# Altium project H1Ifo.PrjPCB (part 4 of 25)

## Sheet IfoTcs1.SchDoc: D1800185
size C; Engineer: Daniel Sigg; DocumentNumber: 7; Revision: 4; SheetNumber: 7; SheetTotal: 8
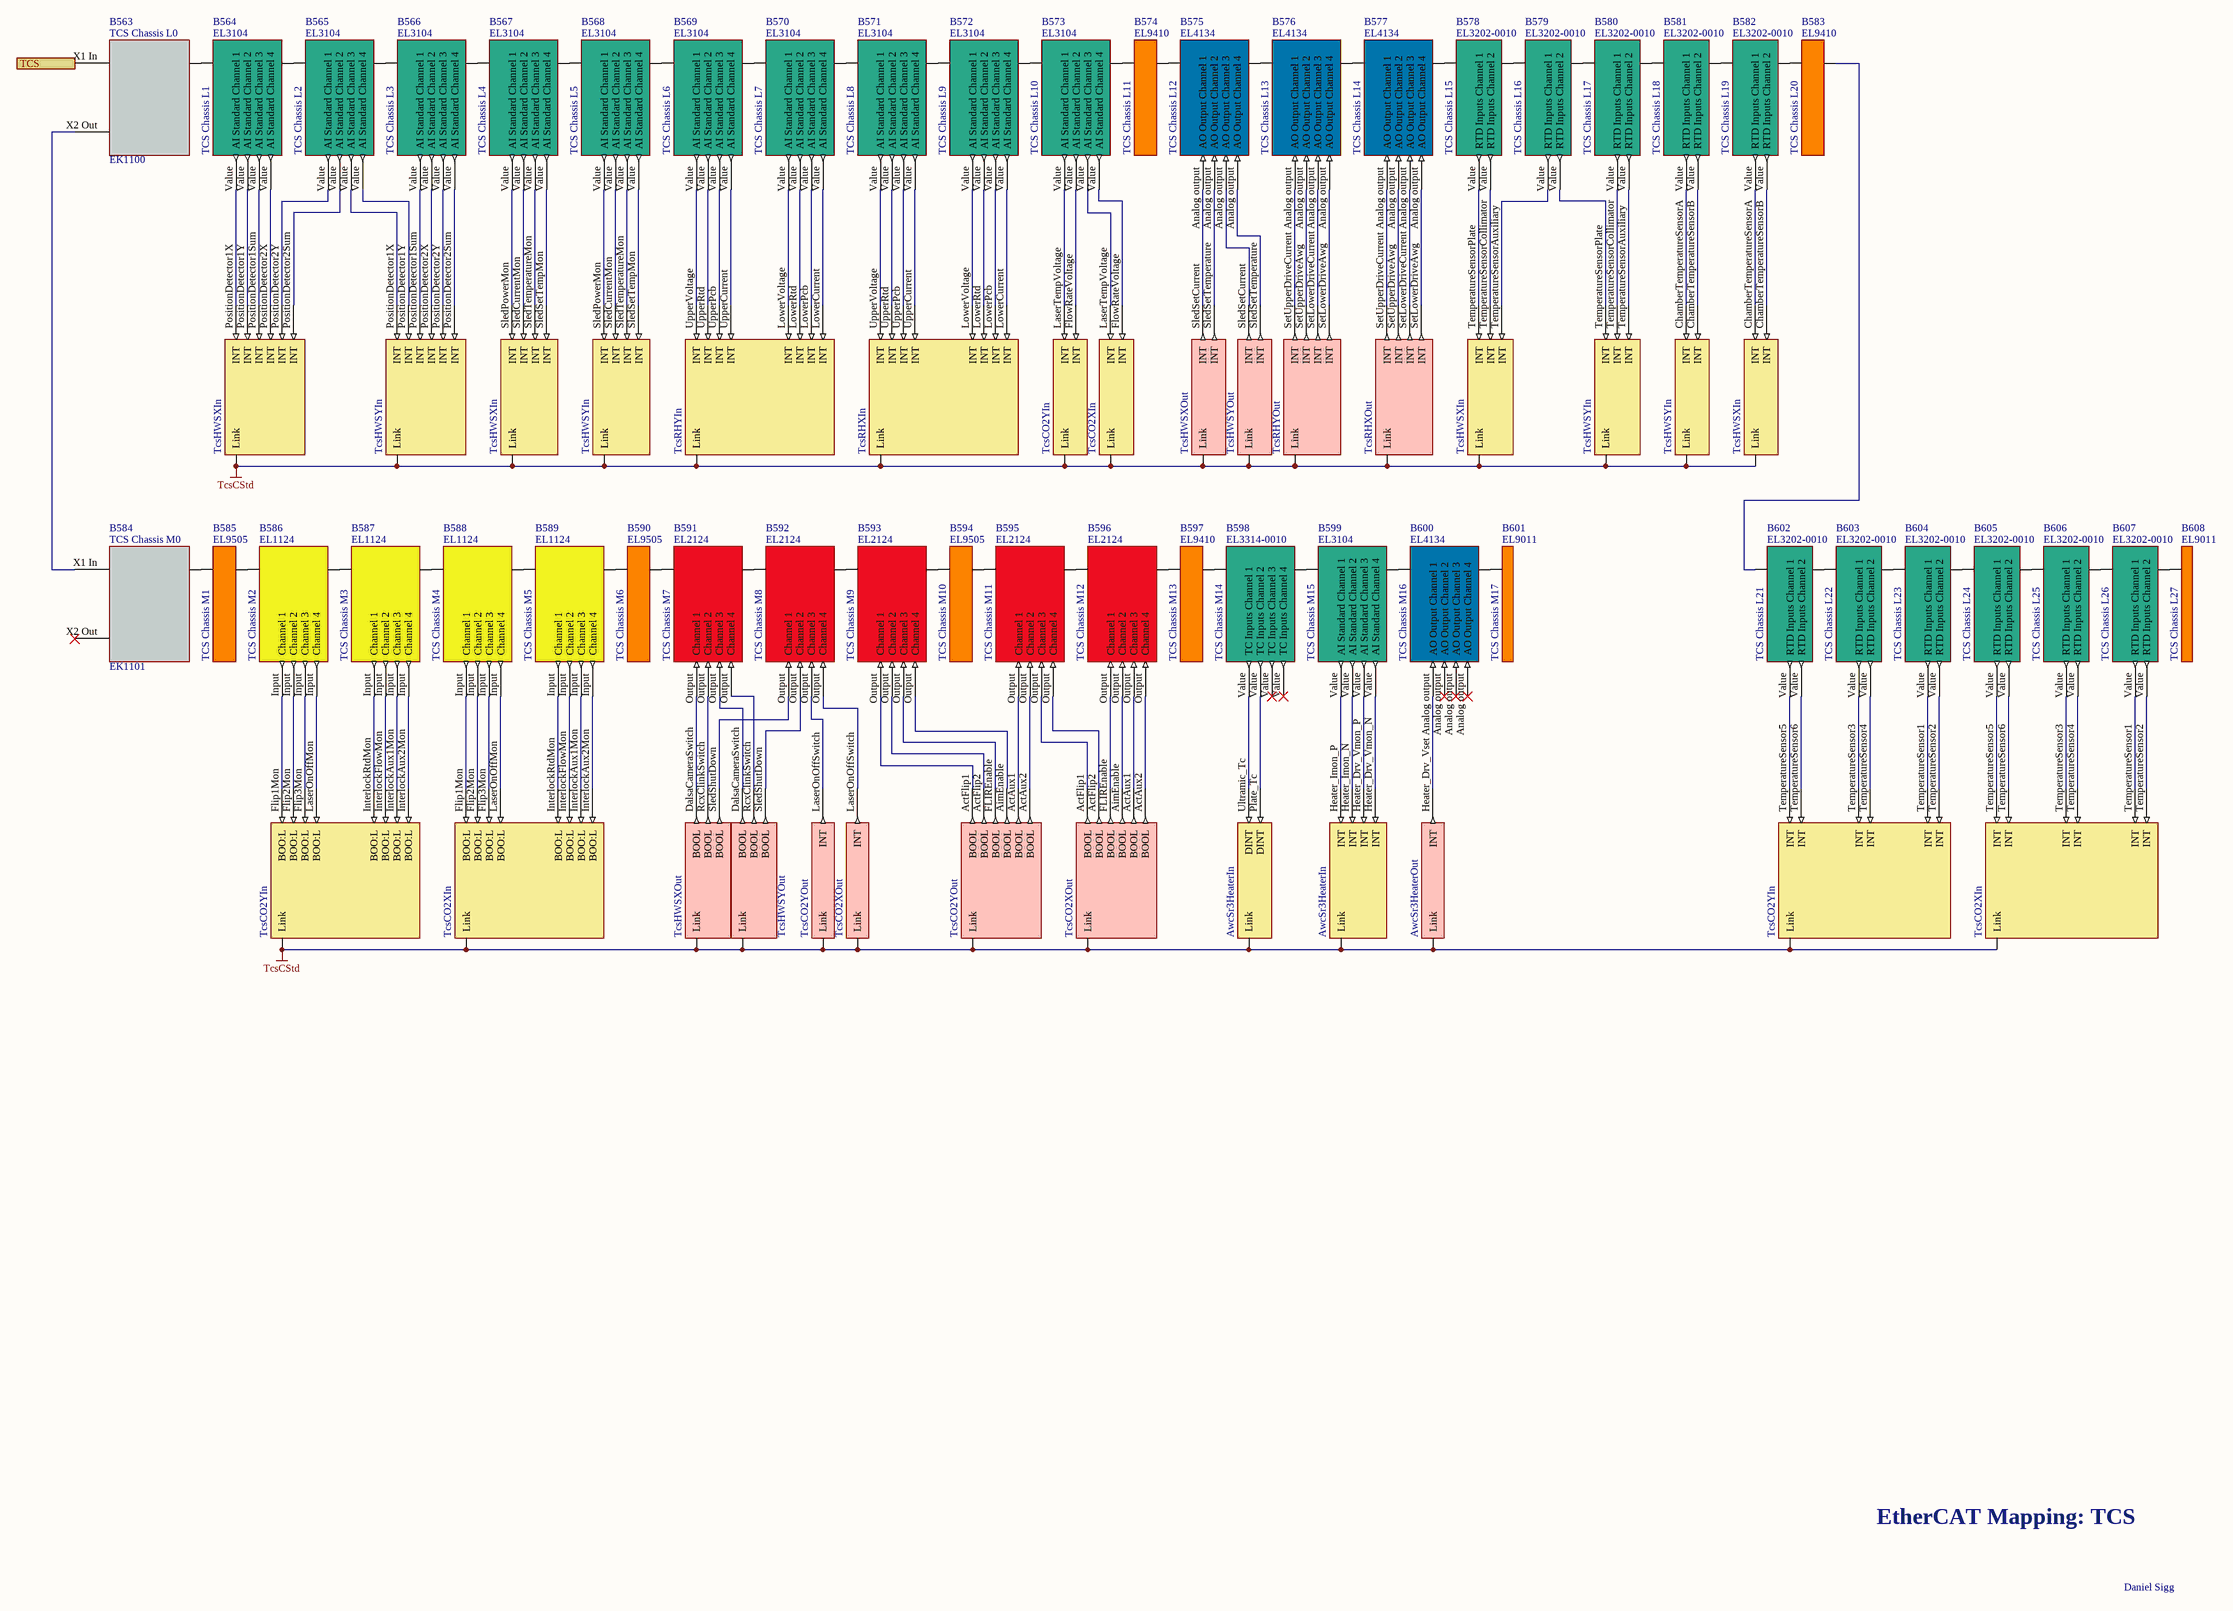
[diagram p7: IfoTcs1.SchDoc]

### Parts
B563  TCS Chassis L0  Part Number: EK1100
B564  TCS Chassis L1  Part Number: EL3104  (mechanical)
B565  TCS Chassis L2  Part Number: EL3104  (mechanical)
B566  TCS Chassis L3  Part Number: EL3104  (mechanical)
B567  TCS Chassis L4  Part Number: EL3104  (mechanical)
B568  TCS Chassis L5  Part Number: EL3104  (mechanical)
B569  TCS Chassis L6  Part Number: EL3104  (mechanical)
B570  TCS Chassis L7  Part Number: EL3104  (mechanical)
B571  TCS Chassis L8  Part Number: EL3104  (mechanical)
B572  TCS Chassis L9  Part Number: EL3104  (mechanical)
B573  TCS Chassis L10  Part Number: EL3104  (mechanical)
B574  TCS Chassis L11  Part Number: EL9410  (mechanical)
B575  TCS Chassis L12  Part Number: EL4134  (mechanical)
B576  TCS Chassis L13  Part Number: EL4134  (mechanical)
B577  TCS Chassis L14  Part Number: EL4134  (mechanical)
B578  TCS Chassis L15  Part Number: EL3202-0010  (mechanical)
B579  TCS Chassis L16  Part Number: EL3202-0010  (mechanical)
B580  TCS Chassis L17  Part Number: EL3202-0010  (mechanical)
B581  TCS Chassis L18  Part Number: EL3202-0010  (mechanical)
B582  TCS Chassis L19  Part Number: EL3202-0010  (mechanical)
B583  TCS Chassis L20  Part Number: EL9410  (mechanical)
B584  TCS Chassis M0  Part Number: EK1101
B585  TCS Chassis M1  Part Number: EL9505  (mechanical)
B586  TCS Chassis M2  Part Number: EL1124  (mechanical)
B587  TCS Chassis M3  Part Number: EL1124  (mechanical)
B588  TCS Chassis M4  Part Number: EL1124  (mechanical)
B589  TCS Chassis M5  Part Number: EL1124  (mechanical)
B590  TCS Chassis M6  Part Number: EL9505  (mechanical)
B591  TCS Chassis M7  Part Number: EL2124  (mechanical)
B592  TCS Chassis M8  Part Number: EL2124  (mechanical)
B593  TCS Chassis M9  Part Number: EL2124  (mechanical)
B594  TCS Chassis M10  Part Number: EL9505  (mechanical)
B595  TCS Chassis M11  Part Number: EL2124  (mechanical)
B596  TCS Chassis M12  Part Number: EL2124  (mechanical)
B597  TCS Chassis M13  Part Number: EL9410  (mechanical)
B598  TCS Chassis M14  Part Number: EL3314-0010  (mechanical)
B599  TCS Chassis M15  Part Number: EL3104  (mechanical)
B600  TCS Chassis M16  Part Number: EL4134  (mechanical)
B601  TCS Chassis M17  Part Number: EL9011  (mechanical)
B602  TCS Chassis L21  Part Number: EL3202-0010  (mechanical)
B603  TCS Chassis L22  Part Number: EL3202-0010  (mechanical)
B604  TCS Chassis L23  Part Number: EL3202-0010  (mechanical)
B605  TCS Chassis L24  Part Number: EL3202-0010  (mechanical)
B606  TCS Chassis L25  Part Number: EL3202-0010  (mechanical)
B607  TCS Chassis L26  Part Number: EL3202-0010  (mechanical)
B608  TCS Chassis L27  Part Number: EL9011  (mechanical)
V519  TcsHWSXIn  (parts A,B,C,D of 4)  (no BOM)
V520  TcsHWSYIn  (parts A,B,C,D of 4)  (no BOM)
V521  TcsRHYIn  (no BOM)
V522  TcsRHXIn  (no BOM)
V523  TcsRHYOut  (no BOM)
V524  TcsRHXOut  (no BOM)
V525  AwcSr3HeaterOut  (no BOM)
V587  TcsHWSXOut  (parts A,B of 2)  (no BOM)
V588  TcsHWSYOut  (parts A,B of 2)  (no BOM)
V589  TcsCO2YIn  (parts A,B,C of 3)  (no BOM)
V590  TcsCO2XIn  (parts A,B,C of 3)  (no BOM)
V591  TcsCO2YOut  (parts A,B of 2)  (no BOM)
V592  TcsCO2XOut  (parts A,B of 2)  (no BOM)
V593  AwcSr3HeaterIn  (parts A,B of 2)  (no BOM)

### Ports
TCS

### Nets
TcsCStd: V519.0(Link) V519.1(Link) V519.2(Link) V519.4(Link) V520.0(Link) V520.1(Link) V520.2(Link) V520.4(Link) V521.0(Link) V522.0(Link) V523.0(Link) V524.0(Link) V525.0(Link) V587.0(Link) V587.1(Link) V588.0(Link) V588.1(Link) V589.0(Link) V589.1(Link) V589.2(Link) V590.0(Link) V590.1(Link) V590.2(Link) V591.0(Link) V591.1(Link) V592.0(Link) V592.1(Link) V593.0(Link) V593.1(Link)
NetB554_X2 Out: B563.X1_In(A) ; port TCS
NetB563_Ebus: B563.Ebus(B) B564.Ebus(A)
NetB563_X2 Out: B563.X2_Out(C) B584.X1_In(A)
NetB564_Ebus: B564.Ebus(B) B565.Ebus(A)
NetB564_Value: B564.Value(AI_Standard_Channel_1) V519.PositionDetector1X(INT)
NetB564_Value: B564.Value(AI_Standard_Channel_2) V519.PositionDetector1Y(INT)  [a separate net that carries the same name]
NetB564_Value: B564.Value(AI_Standard_Channel_3) V519.PositionDetector1Sum(INT)  [a separate net that carries the same name]
NetB564_Value: B564.Value(AI_Standard_Channel_4) V519.PositionDetector2X(INT)  [a separate net that carries the same name]
NetB565_Ebus: B565.Ebus(B) B566.Ebus(A)
NetB565_Value: B565.Value(AI_Standard_Channel_1) V519.PositionDetector2Y(INT)
NetB565_Value: B565.Value(AI_Standard_Channel_2) V519.PositionDetector2Sum(INT)  [a separate net that carries the same name]
NetB565_Value: B565.Value(AI_Standard_Channel_3) V520.PositionDetector1X(INT)  [a separate net that carries the same name]
NetB565_Value: B565.Value(AI_Standard_Channel_4) V520.PositionDetector1Y(INT)  [a separate net that carries the same name]
NetB566_Ebus: B566.Ebus(B) B567.Ebus(A)
NetB566_Value: B566.Value(AI_Standard_Channel_1) V520.PositionDetector1Sum(INT)
NetB566_Value: B566.Value(AI_Standard_Channel_2) V520.PositionDetector2X(INT)  [a separate net that carries the same name]
NetB566_Value: B566.Value(AI_Standard_Channel_3) V520.PositionDetector2Y(INT)  [a separate net that carries the same name]
NetB566_Value: B566.Value(AI_Standard_Channel_4) V520.PositionDetector2Sum(INT)  [a separate net that carries the same name]
NetB567_Ebus: B567.Ebus(B) B568.Ebus(A)
NetB567_Value: B567.Value(AI_Standard_Channel_1) V519.SledPowerMon(INT)
NetB567_Value: B567.Value(AI_Standard_Channel_2) V519.SledCurrentMon(INT)  [a separate net that carries the same name]
NetB567_Value: B567.Value(AI_Standard_Channel_3) V519.SledTemperatureMon(INT)  [a separate net that carries the same name]
NetB567_Value: B567.Value(AI_Standard_Channel_4) V519.SledSetTempMon(INT)  [a separate net that carries the same name]
NetB568_Ebus: B568.Ebus(B) B569.Ebus(A)
NetB568_Value: B568.Value(AI_Standard_Channel_1) V520.SledPowerMon(INT)
NetB568_Value: B568.Value(AI_Standard_Channel_2) V520.SledCurrentMon(INT)  [a separate net that carries the same name]
NetB568_Value: B568.Value(AI_Standard_Channel_3) V520.SledTemperatureMon(INT)  [a separate net that carries the same name]
NetB568_Value: B568.Value(AI_Standard_Channel_4) V520.SledSetTempMon(INT)  [a separate net that carries the same name]
NetB569_Ebus: B569.Ebus(B) B570.Ebus(A)
NetB569_Value: B569.Value(AI_Standard_Channel_1) V521.UpperVoltage(INT)
NetB569_Value: B569.Value(AI_Standard_Channel_2) V521.UpperRtd(INT)  [a separate net that carries the same name]
NetB569_Value: B569.Value(AI_Standard_Channel_3) V521.UpperPcb(INT)  [a separate net that carries the same name]
NetB569_Value: B569.Value(AI_Standard_Channel_4) V521.UpperCurrent(INT)  [a separate net that carries the same name]
NetB570_Ebus: B570.Ebus(B) B571.Ebus(A)
NetB570_Value: B570.Value(AI_Standard_Channel_1) V521.LowerVoltage(INT)
NetB570_Value: B570.Value(AI_Standard_Channel_2) V521.LowerRtd(INT)  [a separate net that carries the same name]
NetB570_Value: B570.Value(AI_Standard_Channel_3) V521.LowerPcb(INT)  [a separate net that carries the same name]
NetB570_Value: B570.Value(AI_Standard_Channel_4) V521.LowerCurrent(INT)  [a separate net that carries the same name]
NetB571_Ebus: B571.Ebus(B) B572.Ebus(A)
NetB571_Value: B571.Value(AI_Standard_Channel_1) V522.UpperVoltage(INT)
NetB571_Value: B571.Value(AI_Standard_Channel_2) V522.UpperRtd(INT)  [a separate net that carries the same name]
NetB571_Value: B571.Value(AI_Standard_Channel_3) V522.UpperPcb(INT)  [a separate net that carries the same name]
NetB571_Value: B571.Value(AI_Standard_Channel_4) V522.UpperCurrent(INT)  [a separate net that carries the same name]
NetB572_Ebus: B572.Ebus(B) B573.Ebus(A)
NetB572_Value: B572.Value(AI_Standard_Channel_1) V522.LowerVoltage(INT)
NetB572_Value: B572.Value(AI_Standard_Channel_2) V522.LowerRtd(INT)  [a separate net that carries the same name]
NetB572_Value: B572.Value(AI_Standard_Channel_3) V522.LowerPcb(INT)  [a separate net that carries the same name]
NetB572_Value: B572.Value(AI_Standard_Channel_4) V522.LowerCurrent(INT)  [a separate net that carries the same name]
NetB573_Ebus: B573.Ebus(B) B574.Ebus(A)
NetB573_Value: B573.Value(AI_Standard_Channel_1) V589.LaserTempVoltage(INT)
NetB573_Value: B573.Value(AI_Standard_Channel_2) V589.FlowRateVoltage(INT)  [a separate net that carries the same name]
NetB573_Value: B573.Value(AI_Standard_Channel_3) V590.LaserTempVoltage(INT)  [a separate net that carries the same name]
NetB573_Value: B573.Value(AI_Standard_Channel_4) V590.FlowRateVoltage(INT)  [a separate net that carries the same name]
NetB574_Ebus: B574.Ebus(B) B575.Ebus(A)
NetB575_Analog output: B575.Analog_output(AO_Output_Channel_1) V587.SledSetCurrent(INT)
NetB575_Analog output: B575.Analog_output(AO_Output_Channel_2) V587.SledSetTemperature(INT)  [a separate net that carries the same name]
NetB575_Analog output: B575.Analog_output(AO_Output_Channel_3) V588.SledSetCurrent(INT)  [a separate net that carries the same name]
NetB575_Analog output: B575.Analog_output(AO_Output_Channel_4) V588.SledSetTemperature(INT)  [a separate net that carries the same name]
NetB575_Ebus: B575.Ebus(B) B576.Ebus(A)
NetB576_Analog output: B576.Analog_output(AO_Output_Channel_1) V523.SetUpperDriveCurrent(INT)
NetB576_Analog output: B576.Analog_output(AO_Output_Channel_2) V523.SetUpperDriveAwg(INT)  [a separate net that carries the same name]
NetB576_Analog output: B576.Analog_output(AO_Output_Channel_3) V523.SetLowerDriveCurrent(INT)  [a separate net that carries the same name]
NetB576_Analog output: B576.Analog_output(AO_Output_Channel_4) V523.SetLowerDriveAwg(INT)  [a separate net that carries the same name]
NetB576_Ebus: B576.Ebus(B) B577.Ebus(A)
NetB577_Analog output: B577.Analog_output(AO_Output_Channel_1) V524.SetUpperDriveCurrent(INT)
NetB577_Analog output: B577.Analog_output(AO_Output_Channel_2) V524.SetUpperDriveAwg(INT)  [a separate net that carries the same name]
NetB577_Analog output: B577.Analog_output(AO_Output_Channel_3) V524.SetLowerDriveCurrent(INT)  [a separate net that carries the same name]
NetB577_Analog output: B577.Analog_output(AO_Output_Channel_4) V524.SetLowerDriveAwg(INT)  [a separate net that carries the same name]
NetB577_Ebus: B577.Ebus(B) B578.Ebus(A)
NetB578_Ebus: B578.Ebus(B) B579.Ebus(A)
NetB578_Value: B578.Value(RTD_Inputs_Channel_1) V519.TemperatureSensorPlate(INT)
NetB578_Value: B578.Value(RTD_Inputs_Channel_2) V519.TemperatureSensorCollimator(INT)  [a separate net that carries the same name]
NetB579_Ebus: B579.Ebus(B) B580.Ebus(A)
NetB579_Value: B579.Value(RTD_Inputs_Channel_1) V519.TemperatureSensorAuxiliary(INT)
NetB579_Value: B579.Value(RTD_Inputs_Channel_2) V520.TemperatureSensorPlate(INT)  [a separate net that carries the same name]
NetB580_Ebus: B580.Ebus(B) B581.Ebus(A)
NetB580_Value: B580.Value(RTD_Inputs_Channel_1) V520.TemperatureSensorCollimator(INT)
NetB580_Value: B580.Value(RTD_Inputs_Channel_2) V520.TemperatureSensorAuxiliary(INT)  [a separate net that carries the same name]
NetB581_Ebus: B581.Ebus(B) B582.Ebus(A)
NetB581_Value: B581.Value(RTD_Inputs_Channel_1) V520.ChamberTemperatureSensorA(INT)
NetB581_Value: B581.Value(RTD_Inputs_Channel_2) V520.ChamberTemperatureSensorB(INT)  [a separate net that carries the same name]
NetB582_Ebus: B582.Ebus(B) B583.Ebus(A)
NetB582_Value: B582.Value(RTD_Inputs_Channel_1) V519.ChamberTemperatureSensorA(INT)
NetB582_Value: B582.Value(RTD_Inputs_Channel_2) V519.ChamberTemperatureSensorB(INT)  [a separate net that carries the same name]
NetB583_Ebus: B583.Ebus(B) B602.Ebus(A)
NetB584_Ebus: B584.Ebus(B) B585.Ebus(A)
NetB585_Ebus: B585.Ebus(B) B586.Ebus(A)
NetB586_Ebus: B586.Ebus(B) B587.Ebus(A)
NetB586_Input: B586.Input(Channel_1) V589.Flip1Mon(BOO:L)
NetB586_Input: B586.Input(Channel_2) V589.Flip2Mon(BOO:L)  [a separate net that carries the same name]
NetB586_Input: B586.Input(Channel_3) V589.Flip3Mon(BOO:L)  [a separate net that carries the same name]
NetB586_Input: B586.Input(Channel_4) V589.LaserOnOffMon(BOO:L)  [a separate net that carries the same name]
NetB587_Ebus: B587.Ebus(B) B588.Ebus(A)
NetB587_Input: B587.Input(Channel_1) V589.InterlockRtdMon(BOO:L)
NetB587_Input: B587.Input(Channel_2) V589.InterlockFlowMon(BOO:L)  [a separate net that carries the same name]
NetB587_Input: B587.Input(Channel_3) V589.InterlockAux1Mon(BOO:L)  [a separate net that carries the same name]
NetB587_Input: B587.Input(Channel_4) V589.InterlockAux2Mon(BOO:L)  [a separate net that carries the same name]
NetB588_Ebus: B588.Ebus(B) B589.Ebus(A)
NetB588_Input: B588.Input(Channel_1) V590.Flip1Mon(BOO:L)
NetB588_Input: B588.Input(Channel_2) V590.Flip2Mon(BOO:L)  [a separate net that carries the same name]
NetB588_Input: B588.Input(Channel_3) V590.Flip3Mon(BOO:L)  [a separate net that carries the same name]
NetB588_Input: B588.Input(Channel_4) V590.LaserOnOffMon(BOO:L)  [a separate net that carries the same name]
NetB589_Ebus: B589.Ebus(B) B590.Ebus(A)
NetB589_Input: B589.Input(Channel_1) V590.InterlockRtdMon(BOO:L)
NetB589_Input: B589.Input(Channel_2) V590.InterlockFlowMon(BOO:L)  [a separate net that carries the same name]
NetB589_Input: B589.Input(Channel_3) V590.InterlockAux1Mon(BOO:L)  [a separate net that carries the same name]
NetB589_Input: B589.Input(Channel_4) V590.InterlockAux2Mon(BOO:L)  [a separate net that carries the same name]
NetB590_Ebus: B590.Ebus(B) B591.Ebus(A)
NetB591_Ebus: B591.Ebus(B) B592.Ebus(A)
NetB591_Output: B591.Output(Channel_1) V587.DalsaCameraSwitch(BOOL)
NetB591_Output: B591.Output(Channel_2) V587.RcxClinkSwitch(BOOL)  [a separate net that carries the same name]
NetB591_Output: B591.Output(Channel_3) V588.DalsaCameraSwitch(BOOL)  [a separate net that carries the same name]
NetB591_Output: B591.Output(Channel_4) V588.RcxClinkSwitch(BOOL)  [a separate net that carries the same name]
NetB592_Ebus: B592.Ebus(B) B593.Ebus(A)
NetB592_Output: B592.Output(Channel_1) V587.SledShutDown(BOOL)
NetB592_Output: B592.Output(Channel_2) V588.SledShutDown(BOOL)  [a separate net that carries the same name]
NetB592_Output: B592.Output(Channel_3) V591.LaserOnOffSwitch(INT)  [a separate net that carries the same name]
NetB592_Output: B592.Output(Channel_4) V592.LaserOnOffSwitch(INT)  [a separate net that carries the same name]
NetB593_Ebus: B593.Ebus(B) B594.Ebus(A)
NetB593_Output: B593.Output(Channel_1) V591.ActFlip1(BOOL)
NetB593_Output: B593.Output(Channel_2) V591.ActFlip2(BOOL)  [a separate net that carries the same name]
NetB593_Output: B593.Output(Channel_3) V591.FLIREnable(BOOL)  [a separate net that carries the same name]
NetB593_Output: B593.Output(Channel_4) V591.AimEnable(BOOL)  [a separate net that carries the same name]
NetB594_Ebus: B594.Ebus(B) B595.Ebus(A)
NetB595_Ebus: B595.Ebus(B) B596.Ebus(A)
NetB595_Output: B595.Output(Channel_1) V591.ActAux1(BOOL)
NetB595_Output: B595.Output(Channel_2) V591.ActAux2(BOOL)  [a separate net that carries the same name]
NetB595_Output: B595.Output(Channel_3) V592.ActFlip1(BOOL)  [a separate net that carries the same name]
NetB595_Output: B595.Output(Channel_4) V592.ActFlip2(BOOL)  [a separate net that carries the same name]
NetB596_Ebus: B596.Ebus(B) B597.Ebus(A)
NetB596_Output: B596.Output(Channel_1) V592.FLIREnable(BOOL)
NetB596_Output: B596.Output(Channel_2) V592.AimEnable(BOOL)  [a separate net that carries the same name]
NetB596_Output: B596.Output(Channel_3) V592.ActAux1(BOOL)  [a separate net that carries the same name]
NetB596_Output: B596.Output(Channel_4) V592.ActAux2(BOOL)  [a separate net that carries the same name]
NetB597_Ebus: B597.Ebus(B) B598.Ebus(A)
NetB598_Ebus: B598.Ebus(B) B599.Ebus(A)
NetB598_Value: B598.Value(TC_Inputs_Channel_1) V593.Ultramic_Tc(DINT)
NetB598_Value: B598.Value(TC_Inputs_Channel_2) V593.Plate_Tc(DINT)  [a separate net that carries the same name]
NetB599_Ebus: B599.Ebus(B) B600.Ebus(A)
NetB599_Value: B599.Value(AI_Standard_Channel_1) V593.Heater_Imon_P(INT)
NetB599_Value: B599.Value(AI_Standard_Channel_2) V593.Heater_Imon_N(INT)  [a separate net that carries the same name]
NetB599_Value: B599.Value(AI_Standard_Channel_3) V593.Heater_Drv_Vmon_P(INT)  [a separate net that carries the same name]
NetB599_Value: B599.Value(AI_Standard_Channel_4) V593.Heater_Drv_Vmon_N(INT)  [a separate net that carries the same name]
NetB600_Analog output: B600.Analog_output(AO_Output_Channel_1) V525.Heater_Drv_Vset(INT)
NetB600_Ebus: B600.Ebus(B) B601.Ebus(A)
NetB602_Ebus: B602.Ebus(B) B603.Ebus(A)
NetB602_Value: B602.Value(RTD_Inputs_Channel_1) V589.TemperatureSensor5(INT)
NetB602_Value: B602.Value(RTD_Inputs_Channel_2) V589.TemperatureSensor6(INT)  [a separate net that carries the same name]
NetB603_Ebus: B603.Ebus(B) B604.Ebus(A)
NetB603_Value: B603.Value(RTD_Inputs_Channel_1) V589.TemperatureSensor3(INT)
NetB603_Value: B603.Value(RTD_Inputs_Channel_2) V589.TemperatureSensor4(INT)  [a separate net that carries the same name]
NetB604_Ebus: B604.Ebus(B) B605.Ebus(A)
NetB604_Value: B604.Value(RTD_Inputs_Channel_1) V589.TemperatureSensor1(INT)
NetB604_Value: B604.Value(RTD_Inputs_Channel_2) V589.TemperatureSensor2(INT)  [a separate net that carries the same name]
NetB605_Ebus: B605.Ebus(B) B606.Ebus(A)
NetB605_Value: B605.Value(RTD_Inputs_Channel_1) V590.TemperatureSensor5(INT)
NetB605_Value: B605.Value(RTD_Inputs_Channel_2) V590.TemperatureSensor6(INT)  [a separate net that carries the same name]
NetB606_Ebus: B606.Ebus(B) B607.Ebus(A)
NetB606_Value: B606.Value(RTD_Inputs_Channel_1) V590.TemperatureSensor3(INT)
NetB606_Value: B606.Value(RTD_Inputs_Channel_2) V590.TemperatureSensor4(INT)  [a separate net that carries the same name]
NetB607_Ebus: B607.Ebus(B) B608.Ebus(A)
NetB607_Value: B607.Value(RTD_Inputs_Channel_1) V590.TemperatureSensor1(INT)
NetB607_Value: B607.Value(RTD_Inputs_Channel_2) V590.TemperatureSensor2(INT)  [a separate net that carries the same name]

Not connected (* = marked no-connect by the designer): B584 X2 Out(C)*

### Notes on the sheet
- EtherCAT Mapping: TCS
- Daniel Sigg

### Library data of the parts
B563 = CouplerEK1100: EtherCAT Coupler; Rail: Left; BoxNextB: RPKXFNAN; BoxNextC: AFLHRHXW; BoxPrev: YQKRVLKQ; PortPrevFull: 1029/C; PortPrevShort: C 'X2 Out'; Fullname: TIID^Vertex PSL TCS (EtherCAT)^TCS Chassis L0 (EK1100); BoxPorts: Junction; BoxAddr: 1036; Disabled: False
B564 = TerminalEL3104: EtherCAT Terminal EL3104 4-chn Analog Input; Rail: Left; BoxNextB: NIWXNMXD; BoxPrev: TXISYRED; PortPrevFull: 1036/B; PortPrevShort: B; Fullname: TIID^Vertex PSL TCS (EtherCAT)^TCS Chassis L0 (EK1100)^TCS Chassis L1 (EL3104); BoxAddr: 1037; Disabled: False
B565 = TerminalEL3104: EtherCAT Terminal EL3104 4-chn Analog Input; Rail: Left; BoxNextB: GLXVAIIR; BoxPrev: RPKXFNAN; PortPrevFull: 1037/B; PortPrevShort: B; Fullname: TIID^Vertex PSL TCS (EtherCAT)^TCS Chassis L0 (EK1100)^TCS Chassis L2 (EL3104); BoxAddr: 1038; Disabled: False
B566 = TerminalEL3104: EtherCAT Terminal EL3104 4-chn Analog Input; Rail: Left; BoxNextB: KHCSPGAM; BoxPrev: NIWXNMXD; PortPrevFull: 1038/B; PortPrevShort: B; Fullname: TIID^Vertex PSL TCS (EtherCAT)^TCS Chassis L0 (EK1100)^TCS Chassis L3 (EL3104); BoxAddr: 1039; Disabled: False
B567 = TerminalEL3104: EtherCAT Terminal EL3104 4-chn Analog Input; Rail: Left; BoxNextB: HVTYPABG; BoxPrev: GLXVAIIR; PortPrevFull: 1039/B; PortPrevShort: B; Fullname: TIID^Vertex PSL TCS (EtherCAT)^TCS Chassis L0 (EK1100)^TCS Chassis L4 (EL3104); BoxAddr: 1040; Disabled: False
B568 = TerminalEL3104: EtherCAT Terminal EL3104 4-chn Analog Input; Rail: Left; BoxNextB: HKOOHFWT; BoxPrev: KHCSPGAM; PortPrevFull: 1040/B; PortPrevShort: B; Fullname: TIID^Vertex PSL TCS (EtherCAT)^TCS Chassis L0 (EK1100)^TCS Chassis L5 (EL3104); BoxAddr: 1041; Disabled: False
B569 = TerminalEL3104: EtherCAT Terminal EL3104 4-chn Analog Input; Rail: Left; BoxNextB: OSHVEIQU; BoxPrev: HVTYPABG; PortPrevFull: 1041/B; PortPrevShort: B; Fullname: TIID^Vertex PSL TCS (EtherCAT)^TCS Chassis L0 (EK1100)^TCS Chassis L6 (EL3104); BoxAddr: 1042; Disabled: False
B570 = TerminalEL3104: EtherCAT Terminal EL3104 4-chn Analog Input; Rail: Left; BoxNextB: BLAUTCRY; BoxPrev: HKOOHFWT; PortPrevFull: 1042/B; PortPrevShort: B; Fullname: TIID^Vertex PSL TCS (EtherCAT)^TCS Chassis L0 (EK1100)^TCS Chassis L7 (EL3104); BoxAddr: 1043; Disabled: False
B571 = TerminalEL3104: EtherCAT Terminal EL3104 4-chn Analog Input; Rail: Left; BoxNextB: MMVLTAPN; BoxPrev: OSHVEIQU; PortPrevFull: 1043/B; PortPrevShort: B; Fullname: TIID^Vertex PSL TCS (EtherCAT)^TCS Chassis L0 (EK1100)^TCS Chassis L8 (EL3104); BoxAddr: 1044; Disabled: False
B572 = TerminalEL3104: EtherCAT Terminal EL3104 4-chn Analog Input; Rail: Left; BoxNextB: JDJGMYCS; BoxPrev: BLAUTCRY; PortPrevFull: 1044/B; PortPrevShort: B; Fullname: TIID^Vertex PSL TCS (EtherCAT)^TCS Chassis L0 (EK1100)^TCS Chassis L9 (EL3104); BoxAddr: 1045; Disabled: False
B573 = TerminalEL3104: EtherCAT Terminal EL3104 4-chn Analog Input; Rail: Left; BoxNextB: RMAMIKNJ; BoxPrev: MMVLTAPN; PortPrevFull: 1045/B; PortPrevShort: B; Fullname: TIID^Vertex PSL TCS (EtherCAT)^TCS Chassis L0 (EK1100)^TCS Chassis L10 (EL3104); BoxAddr: 1046; Disabled: False
B574 = TerminalEL9410: EtherCAT Terminal EL9410 Power; Rail: Left; BoxNextB: SUNPOJLU; BoxPrev: JDJGMYCS; PortPrevFull: 1046/B; PortPrevShort: B; Fullname: TIID^Vertex PSL TCS (EtherCAT)^TCS Chassis L0 (EK1100)^TCS Chassis L11 (EL9410); BoxAddr: 1047; Disabled: False
B575 = TerminalEL4134: EtherCAT Terminal EL4134 4-chn Analog Ouput; Rail: Left; BoxNextB: SMRUYUTJ; BoxPrev: RMAMIKNJ; PortPrevFull: 1047/B; PortPrevShort: B; Fullname: TIID^Vertex PSL TCS (EtherCAT)^TCS Chassis L0 (EK1100)^TCS Chassis L12 (EL4134); BoxAddr: 1048; Disabled: False
B576 = TerminalEL4134: EtherCAT Terminal EL4134 4-chn Analog Ouput; Rail: Left; BoxNextB: AWCAPCGI; BoxPrev: SUNPOJLU; PortPrevFull: 1048/B; PortPrevShort: B; Fullname: TIID^Vertex PSL TCS (EtherCAT)^TCS Chassis L0 (EK1100)^TCS Chassis L13 (EL4134); BoxAddr: 1049; Disabled: False
B577 = TerminalEL4134: EtherCAT Terminal EL4134 4-chn Analog Ouput; Rail: Left; BoxNextB: OJTHNFAQ; BoxPrev: SMRUYUTJ; PortPrevFull: 1049/B; PortPrevShort: B; Fullname: TIID^Vertex PSL TCS (EtherCAT)^TCS Chassis L0 (EK1100)^TCS Chassis L14 (EL4134); BoxAddr: 1050; Disabled: False
B578 = TerminalEL3202-0010: EtherCAT Terminal EL3202-0010 2-chn Temperature Input; Rail: Left; BoxNextB: MOJARUYU; BoxPrev: AWCAPCGI; PortPrevFull: 1050/B; PortPrevShort: B; Fullname: TIID^Vertex PSL TCS (EtherCAT)^TCS Chassis L0 (EK1100)^TCS Chassis L15 (EL3202-0010); BoxAddr: 1051; Disabled: False
B579 = TerminalEL3202-0010: EtherCAT Terminal EL3202-0010 2-chn Temperature Input; Rail: Left; BoxNextB: MFFLVSXN; BoxPrev: OJTHNFAQ; PortPrevFull: 1051/B; PortPrevShort: B; Fullname: TIID^Vertex PSL TCS (EtherCAT)^TCS Chassis L0 (EK1100)^TCS Chassis L16 (EL3202-0010); BoxAddr: 1052; Disabled: False
B580 = TerminalEL3202-0010: EtherCAT Terminal EL3202-0010 2-chn Temperature Input; Rail: Left; BoxNextB: HGFTALQY; BoxPrev: MOJARUYU; PortPrevFull: 1052/B; PortPrevShort: B; Fullname: TIID^Vertex PSL TCS (EtherCAT)^TCS Chassis L0 (EK1100)^TCS Chassis L17 (EL3202-0010); BoxAddr: 1053; Disabled: False
B581 = TerminalEL3202-0010: EtherCAT Terminal EL3202-0010 2-chn Temperature Input; Rail: Left; BoxNextB: JAITAHYA; BoxPrev: MFFLVSXN; PortPrevFull: 1053/B; PortPrevShort: B; Fullname: TIID^Vertex PSL TCS (EtherCAT)^TCS Chassis L0 (EK1100)^TCS Chassis L18 (EL3202-0010); BoxAddr: 1054; Disabled: False
B582 = TerminalEL3202-0010: EtherCAT Terminal EL3202-0010 2-chn Temperature Input; Rail: Left; BoxNextB: CDJPIMFN; BoxPrev: HGFTALQY; PortPrevFull: 1054/B; PortPrevShort: B; Fullname: TIID^Vertex PSL TCS (EtherCAT)^TCS Chassis L0 (EK1100)^TCS Chassis L19 (EL3202-0010); BoxAddr: 1055; Disabled: False
B583 = TerminalEL9410: EtherCAT Terminal EL9410 Power; Rail: Left; BoxNextB: SDDPRSCB; BoxPrev: JAITAHYA; PortPrevFull: 1055/B; PortPrevShort: B; Fullname: TIID^Vertex PSL TCS (EtherCAT)^TCS Chassis L0 (EK1100)^TCS Chassis L20 (EL9410); BoxAddr: 1056; Disabled: False
B584 = CouplerEK1101: EtherCAT Coupler; Rail: Middle; BoxNextB: HWXYPDPR; BoxPrev: TXISYRED; PortPrevFull: 1036/C; PortPrevShort: C 'X2 Out'; Fullname: TIID^Vertex PSL TCS (EtherCAT)^TCS Chassis M0 (EK1101); BoxPorts: Junction; BoxAddr: 1063; Disabled: False
B585 = TerminalEL9505: EtherCAT Terminal EL9505 Power supply terminal 5 V DC; Rail: Middle; BoxNextB: MKPJPOPN; BoxPrev: AFLHRHXW; PortPrevFull: 1063/B; PortPrevShort: B; Fullname: TIID^Vertex PSL TCS (EtherCAT)^TCS Chassis M0 (EK1101)^TCS Chassis M1 (EL9505); BoxAddr: 1064; Disabled: False
B586 = TerminalEL1124: EtherCAT Terminal EL1124 4-chn Digital Input; Rail: Middle; BoxNextB: QXFFSALT; BoxPrev: HWXYPDPR; PortPrevFull: 1064/B; PortPrevShort: B; Fullname: TIID^Vertex PSL TCS (EtherCAT)^TCS Chassis M0 (EK1101)^TCS Chassis M2 (EL1124); BoxAddr: 1065; Disabled: False
B587 = TerminalEL1124: EtherCAT Terminal EL1124 4-chn Digital Input; Rail: Middle; BoxNextB: SVPCSIRV; BoxPrev: MKPJPOPN; PortPrevFull: 1065/B; PortPrevShort: B; Fullname: TIID^Vertex PSL TCS (EtherCAT)^TCS Chassis M0 (EK1101)^TCS Chassis M3 (EL1124); BoxAddr: 1066; Disabled: False
B588 = TerminalEL1124: EtherCAT Terminal EL1124 4-chn Digital Input; Rail: Middle; BoxNextB: JWKQWUTT; BoxPrev: QXFFSALT; PortPrevFull: 1066/B; PortPrevShort: B; Fullname: TIID^Vertex PSL TCS (EtherCAT)^TCS Chassis M0 (EK1101)^TCS Chassis M4 (EL1124); BoxAddr: 1067; Disabled: False
B589 = TerminalEL1124: EtherCAT Terminal EL1124 4-chn Digital Input; Rail: Middle; BoxNextB: IYLMJPXM; BoxPrev: SVPCSIRV; PortPrevFull: 1067/B; PortPrevShort: B; Fullname: TIID^Vertex PSL TCS (EtherCAT)^TCS Chassis M0 (EK1101)^TCS Chassis M5 (EL1124); BoxAddr: 1068; Disabled: False
B590 = TerminalEL9505: EtherCAT Terminal EL9505 Power supply terminal 5 V DC; Rail: Middle; BoxNextB: YCUWVHHP; BoxPrev: JWKQWUTT; PortPrevFull: 1068/B; PortPrevShort: B; Fullname: TIID^Vertex PSL TCS (EtherCAT)^TCS Chassis M0 (EK1101)^TCS Chassis M6 (EL9505); BoxAddr: 1069; Disabled: False
B591 = TerminalEL2124: EtherCAT Terminal EL2124 4-chn Digital Ouput; Rail: Middle; BoxNextB: GAMKOKTP; BoxPrev: IYLMJPXM; PortPrevFull: 1069/B; PortPrevShort: B; Fullname: TIID^Vertex PSL TCS (EtherCAT)^TCS Chassis M0 (EK1101)^TCS Chassis M7 (EL2124); BoxAddr: 1070; Disabled: False
B592 = TerminalEL2124: EtherCAT Terminal EL2124 4-chn Digital Ouput; Rail: Middle; BoxNextB: NPKDDJXI; BoxPrev: YCUWVHHP; PortPrevFull: 1070/B; PortPrevShort: B; Fullname: TIID^Vertex PSL TCS (EtherCAT)^TCS Chassis M0 (EK1101)^TCS Chassis M8 (EL2124); BoxAddr: 1071; Disabled: False
B593 = TerminalEL2124: EtherCAT Terminal EL2124 4-chn Digital Ouput; Rail: Middle; BoxNextB: AOTGPCYL; BoxPrev: GAMKOKTP; PortPrevFull: 1071/B; PortPrevShort: B; Fullname: TIID^Vertex PSL TCS (EtherCAT)^TCS Chassis M0 (EK1101)^TCS Chassis M9 (EL2124); BoxAddr: 1072; Disabled: False
B594 = TerminalEL9505: EtherCAT Terminal EL9505 Power supply terminal 5 V DC; Rail: Middle; BoxNextB: KEBBVHHF; BoxPrev: NPKDDJXI; PortPrevFull: 1072/B; PortPrevShort: B; Fullname: TIID^Vertex PSL TCS (EtherCAT)^TCS Chassis M0 (EK1101)^TCS Chassis M10 (EL9505); BoxAddr: 1073; Disabled: False
B595 = TerminalEL2124: EtherCAT Terminal EL2124 4-chn Digital Ouput; Rail: Middle; BoxNextB: SXFBHKKD; BoxPrev: AOTGPCYL; PortPrevFull: 1073/B; PortPrevShort: B; Fullname: TIID^Vertex PSL TCS (EtherCAT)^TCS Chassis M0 (EK1101)^TCS Chassis M11 (EL2124); BoxAddr: 1074; Disabled: False
B596 = TerminalEL2124: EtherCAT Terminal EL2124 4-chn Digital Ouput; Rail: Middle; BoxNextB: YBJXBHDF; BoxPrev: KEBBVHHF; PortPrevFull: 1074/B; PortPrevShort: B; Fullname: TIID^Vertex PSL TCS (EtherCAT)^TCS Chassis M0 (EK1101)^TCS Chassis M12 (EL2124); BoxAddr: 1075; Disabled: False
B597 = TerminalEL9410: EtherCAT Terminal EL9410 Power; Rail: Middle; BoxNextB: BYPDIGFH; BoxPrev: SXFBHKKD; PortPrevFull: 1075/B; PortPrevShort: B; Fullname: TIID^Vertex PSL TCS (EtherCAT)^TCS Chassis M0 (EK1101)^TCS Chassis M13 (EL9410); BoxAddr: 1076; Disabled: False
B598 = TerminalEL3314: EtherCAT Terminal EL3314 4-channel thermocouple input terminal with open-circuit recognition; Rail: Middle; BoxNextB: YOARTNQE; BoxPrev: YBJXBHDF; PortPrevFull: 1076/B; PortPrevShort: B; Fullname: TIID^Vertex PSL TCS (EtherCAT)^TCS Chassis M0 (EK1101)^TCS Chassis M14 (EL3314-0010); BoxAddr: 1077; Disabled: False
B599 = TerminalEL3104: EtherCAT Terminal EL3104 4-chn Analog Input; Rail: Middle; BoxNextB: JPABTYDV; BoxPrev: BYPDIGFH; PortPrevFull: 1077/B; PortPrevShort: B; Fullname: TIID^Vertex PSL TCS (EtherCAT)^TCS Chassis M0 (EK1101)^TCS Chassis M15 (EL3104); BoxAddr: 1078; Disabled: False
B600 = TerminalEL4134: EtherCAT Terminal EL4134 4-chn Analog Ouput; Rail: Middle; BoxNextB: HJNNXFHH; BoxPrev: YOARTNQE; PortPrevFull: 1078/B; PortPrevShort: B; Fullname: TIID^Vertex PSL TCS (EtherCAT)^TCS Chassis M0 (EK1101)^TCS Chassis M16 (EL4134); BoxAddr: 1079; Disabled: False
B601 = TerminalEL9011: EtherCAT Terminal EL9011 End; BoxType: TerminalPassive; Rail: Middle; BoxPrev: JPABTYDV; PortPrevShort: B; Fullname: TIID^Vertex PSL TCS (EtherCAT)^TCS Chassis M0 (EK1101)^TCS Chassis M17 (EL9011); Disabled: False
B602 = TerminalEL3202-0010: EtherCAT Terminal EL3202-0010 2-chn Temperature Input; Rail: Left; BoxNextB: KHKAPHRU; BoxPrev: CDJPIMFN; PortPrevFull: 1056/B; PortPrevShort: B; Fullname: TIID^Vertex PSL TCS (EtherCAT)^TCS Chassis L0 (EK1100)^TCS Chassis L21 (EL3202-0010); BoxAddr: 1057; Disabled: False
B603 = TerminalEL3202-0010: EtherCAT Terminal EL3202-0010 2-chn Temperature Input; Rail: Left; BoxNextB: ATECRSSU; BoxPrev: SDDPRSCB; PortPrevFull: 1057/B; PortPrevShort: B; Fullname: TIID^Vertex PSL TCS (EtherCAT)^TCS Chassis L0 (EK1100)^TCS Chassis L22 (EL3202-0010); BoxAddr: 1058; Disabled: False
B604 = TerminalEL3202-0010: EtherCAT Terminal EL3202-0010 2-chn Temperature Input; Rail: Left; BoxNextB: WXAREYUD; BoxPrev: KHKAPHRU; PortPrevFull: 1058/B; PortPrevShort: B; Fullname: TIID^Vertex PSL TCS (EtherCAT)^TCS Chassis L0 (EK1100)^TCS Chassis L23 (EL3202-0010); BoxAddr: 1059; Disabled: False
B605 = TerminalEL3202-0010: EtherCAT Terminal EL3202-0010 2-chn Temperature Input; Rail: Left; BoxNextB: LHSVLEUD; BoxPrev: ATECRSSU; PortPrevFull: 1059/B; PortPrevShort: B; Fullname: TIID^Vertex PSL TCS (EtherCAT)^TCS Chassis L0 (EK1100)^TCS Chassis L24 (EL3202-0010); BoxAddr: 1060; Disabled: False
B606 = TerminalEL3202-0010: EtherCAT Terminal EL3202-0010 2-chn Temperature Input; Rail: Left; BoxNextB: NRKYEUUH; BoxPrev: WXAREYUD; PortPrevFull: 1060/B; PortPrevShort: B; Fullname: TIID^Vertex PSL TCS (EtherCAT)^TCS Chassis L0 (EK1100)^TCS Chassis L25 (EL3202-0010); BoxAddr: 1061; Disabled: False
B607 = TerminalEL3202-0010: EtherCAT Terminal EL3202-0010 2-chn Temperature Input; Rail: Left; BoxNextB: DHUGWVTV; BoxPrev: LHSVLEUD; PortPrevFull: 1061/B; PortPrevShort: B; Fullname: TIID^Vertex PSL TCS (EtherCAT)^TCS Chassis L0 (EK1100)^TCS Chassis L26 (EL3202-0010); BoxAddr: 1062; Disabled: False
B608 = TerminalEL9011: EtherCAT Terminal EL9011 End; BoxType: TerminalPassive; Rail: Left; BoxPrev: NRKYEUUH; PortPrevShort: B; Fullname: TIID^Vertex PSL TCS (EtherCAT)^TCS Chassis L0 (EK1100)^TCS Chassis L27 (EL9011); Disabled: False
V519 V520 = HartmannSensor_HartmannSensorInStruct: HartmannSensorInStruct; BoxType: Variable; Instance: H1TcsCorner Instance; PLC: H1TcsCorner; Task: TcsCStd
V521 V522 = RingHeater_RingHeaterInStruct: RingHeaterInStruct; BoxType: Variable; Instance: H1TcsCorner Instance; PLC: H1TcsCorner; Task: TcsCStd
V523 V524 = RingHeater_RingHeaterOutStruct: RingHeaterOutStruct; BoxType: Variable; Instance: H1TcsCorner Instance; PLC: H1TcsCorner; Task: TcsCStd
V525 = AWC_AWCHeaterOutStruct: AWCHeaterOutStruct; BoxType: Variable; Instance: H1TcsCorner Instance; PLC: H1TcsCorner; Task: TcsCStd
V587 V588 = HartmannSensor_HartmannSensorOutStruct: HartmannSensorOutStruct; BoxType: Variable; Instance: H1TcsCorner Instance; PLC: H1TcsCorner; Task: TcsCStd
V589 V590 = CO2_CO2InStruct: CO2InStruct; BoxType: Variable; Instance: H1TcsCorner Instance; PLC: H1TcsCorner; Task: TcsCStd
V591 V592 = CO2_CO2OutStruct: CO2OutStruct; BoxType: Variable; Instance: H1TcsCorner Instance; PLC: H1TcsCorner; Task: TcsCStd
V593 = AWC_AWCHeaterInStruct: AWCHeaterInStruct; BoxType: Variable; Instance: H1TcsCorner Instance; PLC: H1TcsCorner; Task: TcsCStd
